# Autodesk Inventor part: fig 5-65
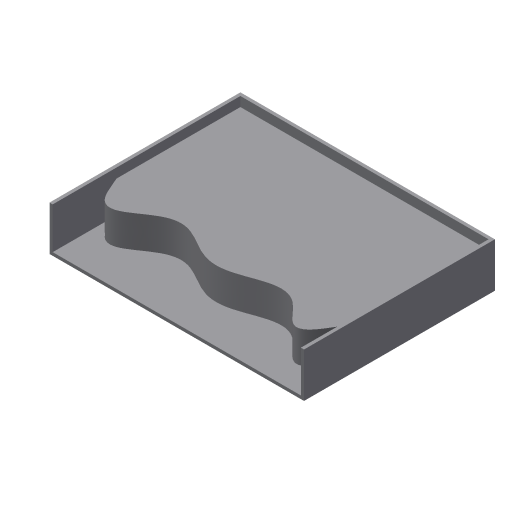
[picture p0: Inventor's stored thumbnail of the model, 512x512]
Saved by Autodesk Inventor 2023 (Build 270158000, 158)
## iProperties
Created: 2004-05
Part Number: fig 5-65
Document SubType Name: Modeling
Designer: CADCIM Technologies
Manufacturer: Standard
Standards Organization: Custom
Density: 1 g/cm^3
Material: Generic
Appearance: Default
Author: CADCIM Technologies
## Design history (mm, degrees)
sketch "Sketch1"
  geometry: L1 (-40, -30)-(40, -30); L2 (40, -30)-(40, 30); L3 (40, 30)-(-40, 30); L4 (-40, 30)-(-40, -30); 1 further point
  constraints: 8 end point, 2 parallel, 1 horizontal, 1 perpendicular, 1 other
  dimensions: "d0" = 80 distance of L1.start L1.end; "d1" = 60 distance of L3.end L1.start; "d2" = 30 distance from line of point (0, 0) L1; "d3" = 40 distance from line of point (0, 0) L4
extrude "Extrusion1" new body sketch "Sketch1" distance "d4" = 14; taper "d5" = 0 deg
shell "Shell1" dims "d6" = 1
workplane "Work Plane1"
sketch "Sketch2"
  geometry: L1 (78, -13)-(78, -11.813); L2 (0, -11.813)-(0, -13); L3 (0, -13)-(78, -13); L4 (0, -11.813)-(17.826, -3.295); L5 (17.826, -3.295)-(60.174, -3.295); L6 (60.174, -3.295)-(78, -11.813); L7 (79, -13.795)-(78, -13.795); L8 (78, 0)-(78, -13) reference; L9 (0, -13)-(0, 0) reference; L10 (78, -13)-(0, -13) reference
  constraints: 14 end point, 3 collinear, 2 equal length, 2 vertical, 1 horizontal alignment, 1 parallel, 1 point on line
extrude "Extrusion2" join sketch "Sketch2" stored distance "d8" = 14; taper "d9" = 0 deg
workplane "Work Plane2"
sketch "Sketch4"
  geometry: 7 further points
  constraints: 7 other
extrude "Extrusion9" join sketch "Sketch4" distance "d35" = 10; taper "d36" = 0 deg
body "Solid1"
other parameters: "d7" = 23, "d18" = 4
